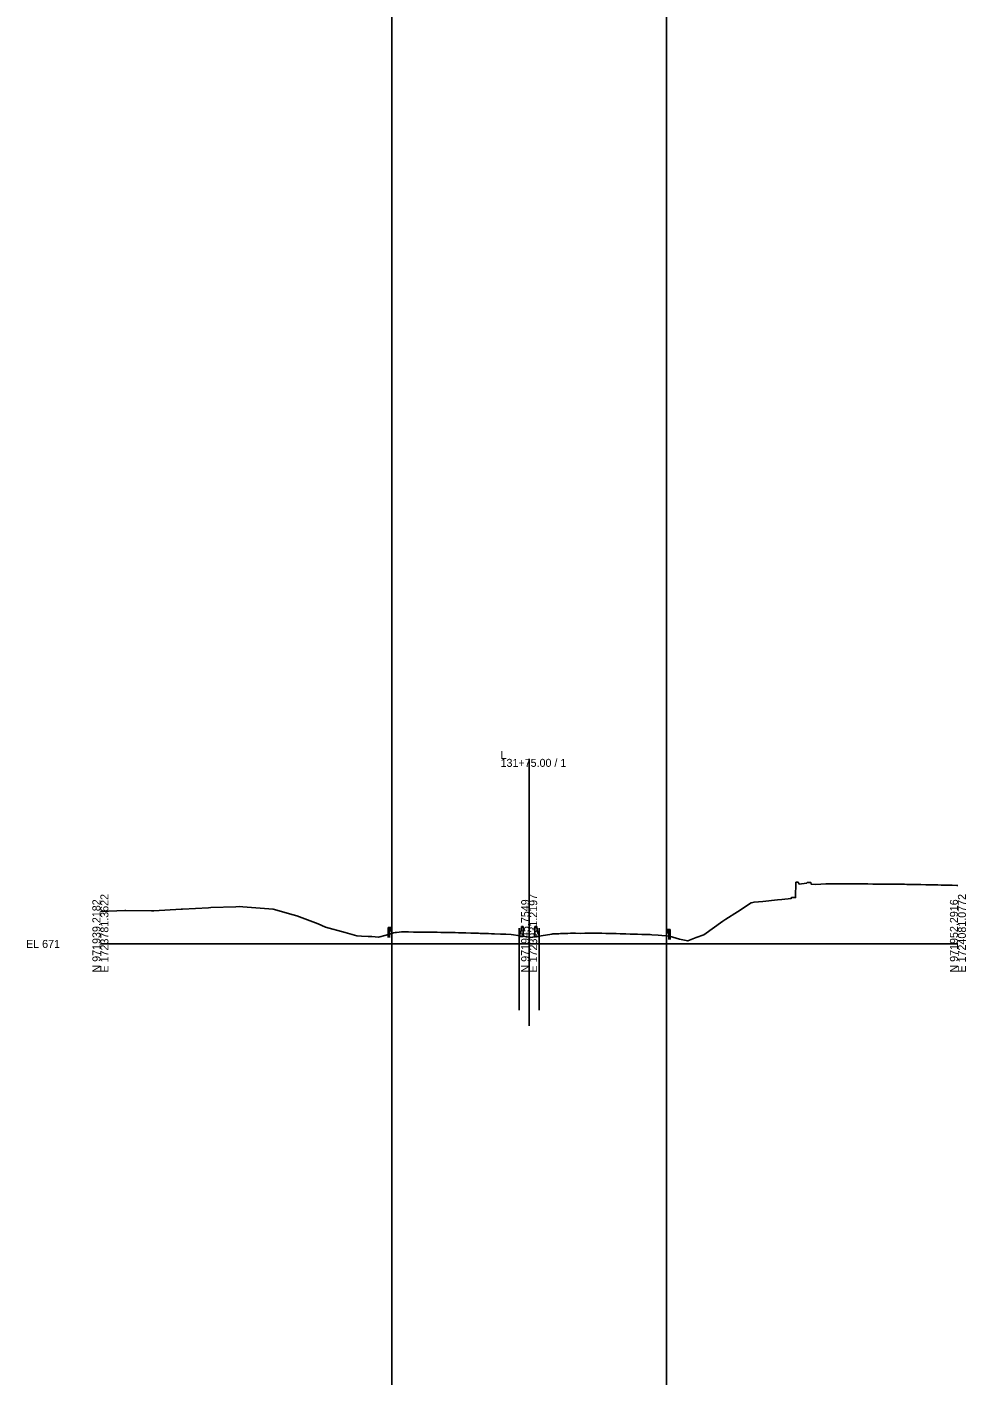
# Model space of a CAD drawing. Extents: x -26 to 303, y -29 to 15026.
# Drawn here: x -25.7 to 302.8, y 6849.2 to 7320.8 of the extents above; entities that cross this region are included whole.
import ezdxf

# ---------------------------------------------------------------- set-up
doc = ezdxf.new("R2010")
doc.units = 0
for name, color, linetype in [('Exist Cross Section Cell', 7, 'Continuous'), ('Exist XS Center Line Elevation Label', 7, 'Continuous'), ('Exist XS Ground Line', 7, 'Continuous'), ('Scratch_Level_0', 7, 'Continuous'), ('Typical Guardrail CELL', 7, 'Continuous'), ('Typical Median Barrier CELL', 7, 'Continuous')]:
    doc.layers.add(name, color=color, linetype=linetype)

msp = doc.modelspace()

# ---------------------------------------------------------------- linework, layer by layer
at = {"layer": 'Exist Cross Section Cell'}
for p, q in [((150, 7000), (150, 7064.74)), ((0, 7000), (150, 7000)), ((150, 7000), (300, 7000))]:
    msp.add_line(p, q, dxfattribs=at)
at = {"layer": 'Exist XS Ground Line'}
msp.add_lwpolyline([(0, 7011.32), (8.49, 7011.64), (8.93, 7011.67), (17.91, 7011.61), (18.67, 7011.61), (28.23, 7012.19), (28.68, 7012.19), (37.82, 7012.61), (38.69, 7012.7), (47.41, 7012.99), (48.69, 7013.04), (49.88, 7013), (60.41, 7012.2), (67.47, 7010.15), (68.71, 7009.8), (76.18, 7007.02), (78.72, 7005.91), (85.66, 7003.99), (89.67, 7002.84), (91.33, 7002.67), (93.73, 7002.64), (94.92, 7002.58), (97.25, 7002.39), (99.94, 7003.12), (102.58, 7003.84), (103.14, 7003.98), (103.55, 7004.03), (104.51, 7004.14), (105.32, 7004.18), (107.06, 7004.18), (107.82, 7004.18), (109.48, 7004.16), (110.34, 7004.15), (110.98, 7004.15), (111.31, 7004.16), (111.91, 7004.15), (112.86, 7004.13), (113.91, 7004.12), (115.36, 7004.09), (116.69, 7004.08), (117.86, 7004.07), (119.09, 7004.05), (120.35, 7004.03), (121.97, 7004), (123.06, 7003.98), (124.13, 7003.95), (125.33, 7003.92), (126.95, 7003.87), (127.84, 7003.85), (129.57, 7003.79), (130.34, 7003.77), (132.22, 7003.72), (132.87, 7003.7), (134.51, 7003.65), (135.73, 7003.6), (136.86, 7003.57), (137.87, 7003.54), (140.03, 7003.47), (140.49, 7003.46), (141.81, 7003.44), (143.76, 7003.26), (150, 7002.33), (150.45, 7002.26), (157.94, 7003.45), (158.25, 7003.52), (158.56, 7003.53), (159.28, 7003.55), (160.36, 7003.59), (160.97, 7003.61), (162.89, 7003.66), (163.58, 7003.68), (164.41, 7003.71), (164.9, 7003.71), (165.42, 7003.71), (166.23, 7003.71), (167.89, 7003.7), (169.46, 7003.71), (170.43, 7003.72), (171.46, 7003.71), (172.91, 7003.71), (174.24, 7003.71), (175.42, 7003.71), (176.85, 7003.69), (177.23, 7003.69), (177.91, 7003.67), (179.03, 7003.64), (180.4, 7003.6), (181.89, 7003.57), (182.89, 7003.54), (183.81, 7003.52), (185.39, 7003.47), (187.13, 7003.42), (187.89, 7003.4), (189.41, 7003.35), (190.4, 7003.3), (192.37, 7003.26), (192.9, 7003.24), (195.17, 7003.12), (199.13, 7002.67), (202.61, 7001.69), (205.46, 7001.08), (208.42, 7002.22), (211.07, 7003.2), (217.81, 7007.96), (218.85, 7008.71), (222.85, 7011.25), (227.68, 7014.35), (228.21, 7014.48), (228.7, 7014.62), (231.77, 7014.8), (236.85, 7015.37), (238.43, 7015.56), (241.62, 7015.89), (241.72, 7016.21), (243.22, 7016.2), (243.32, 7021.58), (244.07, 7021.56), (244.41, 7020.94), (247.08, 7021.23), (247.31, 7021.49), (248.19, 7021.49), (248.55, 7021.47), (248.66, 7020.86), (250.34, 7020.8), (253.8, 7020.99), (255.33, 7021.02), (256.13, 7021.02), (256.45, 7021.02), (257.07, 7021.02), (257.5, 7021.01), (258.02, 7021.01), (260.07, 7021), (260.4, 7021), (262.74, 7020.99), (264.68, 7020.99), (265.24, 7020.99), (267.08, 7020.98), (267.76, 7020.97), (268.49, 7020.97), (270.27, 7020.95), (271.02, 7020.94), (272.29, 7020.93), (273.01, 7020.92), (273.51, 7020.92), (275.51, 7020.9), (277.34, 7020.9), (278, 7020.89), (279.58, 7020.87), (280.13, 7020.87), (280.96, 7020.86), (281.28, 7020.85), (282.08, 7020.83), (283.31, 7020.81), (284.84, 7020.79), (285.48, 7020.77), (285.83, 7020.77), (286.97, 7020.75), (288.77, 7020.73), (290.6, 7020.69), (291.52, 7020.67), (293.02, 7020.63), (294.14, 7020.61), (295.52, 7020.58), (297.02, 7020.54), (298.01, 7020.52), (299.63, 7020.48), (300, 7020.47)], dxfattribs=at)
at = {"layer": 'Scratch_Level_0'}
for p, q in [((102, 15009.56), (102, -28.7)), ((198, 15009.56), (198, -28.7)), ((146.46, 7005.5), (146.46, 6976.8)), ((153.54, 7005.5), (153.54, 6976.8)), ((150, 7000), (150, 6971.3)), ((150, 7000), (150, 6971.3))]:
    msp.add_line(p, q, dxfattribs=at)
at = {"layer": 'Typical Guardrail CELL'}
for p, q in [((101.18, 7005.8), (100.68, 7005.8)), ((100.68, 7005.8), (100.68, 7003.32)), ((101.18, 7003.32), (100.68, 7003.32)), ((100.68, 7003.32), (100.68, 7002.31)), ((101.18, 7005.8), (101.18, 7003.32)), ((101.18, 7005.8), (101.68, 7005.8)), ((101.18, 7004.64), (101.68, 7004.64)), ((101.18, 7003.32), (101.18, 7002.31)), ((101.68, 7005.8), (101.68, 7004.64)), ((101.68, 7005.8), (101.97, 7005.6)), ((101.68, 7005.27), (101.97, 7005.47)), ((101.68, 7005.22), (101.68, 7005.27)), ((101.68, 7005.22), (101.68, 7005.18)), ((101.68, 7005.18), (101.97, 7004.98)), ((101.68, 7004.64), (101.97, 7004.85)), ((198.32, 7005.1), (198.03, 7004.9)), ((198.32, 7004.57), (198.03, 7004.77)), ((198.32, 7004.48), (198.03, 7004.27)), ((198.32, 7003.94), (198.03, 7004.15)), ((198.82, 7005.1), (198.32, 7005.1)), ((198.32, 7005.1), (198.32, 7003.94)), ((198.32, 7004.52), (198.32, 7004.57)), ((198.32, 7004.52), (198.32, 7004.48)), ((198.82, 7003.94), (198.32, 7003.94)), ((198.82, 7005.1), (198.82, 7002.62)), ((198.82, 7005.1), (199.32, 7005.1)), ((198.82, 7002.62), (199.32, 7002.62)), ((198.82, 7002.62), (198.82, 7001.61)), ((199.32, 7005.1), (199.32, 7002.62)), ((199.32, 7002.62), (199.32, 7001.61))]:
    msp.add_line(p, q, dxfattribs=at)
for centre, start, end in [((101.92, 7005.54), 304.9888, 54.997), ((101.92, 7004.91), 304.9634, 54.9941), ((198.08, 7004.84), 125.003, 235.0112), ((198.08, 7004.21), 125.0059, 235.0366)]:
    msp.add_arc(centre, 0.0776, start, end, dxfattribs=at)
at = {"layer": 'Typical Median Barrier CELL'}
for p, q in [((146.46, 7003.06), (146.92, 7003.72)), ((146.46, 7002.64), (146.46, 7003.06)), ((147.96, 7002.64), (146.46, 7002.64)), ((147.07, 7004.11), (147.29, 7006.06)), ((147.29, 7006.06), (147.96, 7006.06)), ((147.96, 7006.06), (147.96, 7002.64)), ((152.71, 7006.06), (152.04, 7006.06)), ((152.04, 7006.06), (152.04, 7002.64)), ((152.04, 7002.64), (153.54, 7002.64)), ((152.93, 7004.11), (152.71, 7006.06)), ((153.54, 7003.06), (153.08, 7003.72)), ((153.54, 7002.64), (153.54, 7003.06))]:
    msp.add_line(p, q, dxfattribs=at)
for centre, start, end in [((146.24, 7004.19), 325.0039, 353.9447), ((153.76, 7004.19), 186.0553, 214.9961)]:
    msp.add_arc(centre, 0.833, start, end, dxfattribs=at)

# ---------------------------------------------------------------- texts
at = {"layer": 'Exist Cross Section Cell'}
for s, p in [('131+75.00 / 1', (140, 7061.94)), ('L', (140, 7064.74)), ('EL 671', (-26, 6998.6))]:
    msp.add_text(s, height=2.8, dxfattribs=at).set_placement(p)
for s, p in [('E 1723781.3622', (2.8, 6990)), ('E 1723931.2197', (152.8, 6990)), ('E 1724081.0772', (302.8, 6990)), ('N 971939.2182', (0, 6990)), ('N 971945.7549', (150, 6990)), ('N 971952.2916', (300, 6990))]:
    msp.add_text(s, height=2.8, rotation=90, dxfattribs=at).set_placement(p)
at = {"layer": 'Exist XS Center Line Elevation Label'}
msp.add_text('673.33', height=0.18, dxfattribs=at).set_placement((149.62, 7001.84))

doc.saveas('drawing.dxf')
